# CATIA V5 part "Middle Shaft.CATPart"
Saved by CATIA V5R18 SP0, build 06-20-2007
Part number: Middle shaft
Bounding box of the stored display mesh (mm): x 0 to 100, y -25 to 25, z -24.818 to 24.818
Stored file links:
  D:\Shriniwas\v5_r19\c16_CAT_v5r19\c16_Part\CV Joint\Middle shaft.CATPart
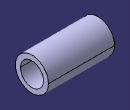
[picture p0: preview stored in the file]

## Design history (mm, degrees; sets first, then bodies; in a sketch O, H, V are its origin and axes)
Body1 (main body)
  Sketch1 on yz-plane, origin (0, 0, 0), H (0, 1, 0), V (0, 0, 1)
    circle A1 centre (0, 0) radius 25
    circle A2 centre (0, 0) radius 17.5
    radius A1 = 25
    radius A2 = 17.5
  Pad1: profile Sketch1, direction (1, 0, 0), length 100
